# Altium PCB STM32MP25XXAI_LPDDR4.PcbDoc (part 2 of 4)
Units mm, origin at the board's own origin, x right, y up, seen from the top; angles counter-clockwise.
Board outline 172 x 137 mm, 4 copper layers (Top Layer, Signal Layer 1, Signal Layer 2, Bottom Layer), stack 1.614 mm thick; 188 components, 144 nets, 1216 pads, 838 vias.
Unrouted connection lines stored in the file: 13.
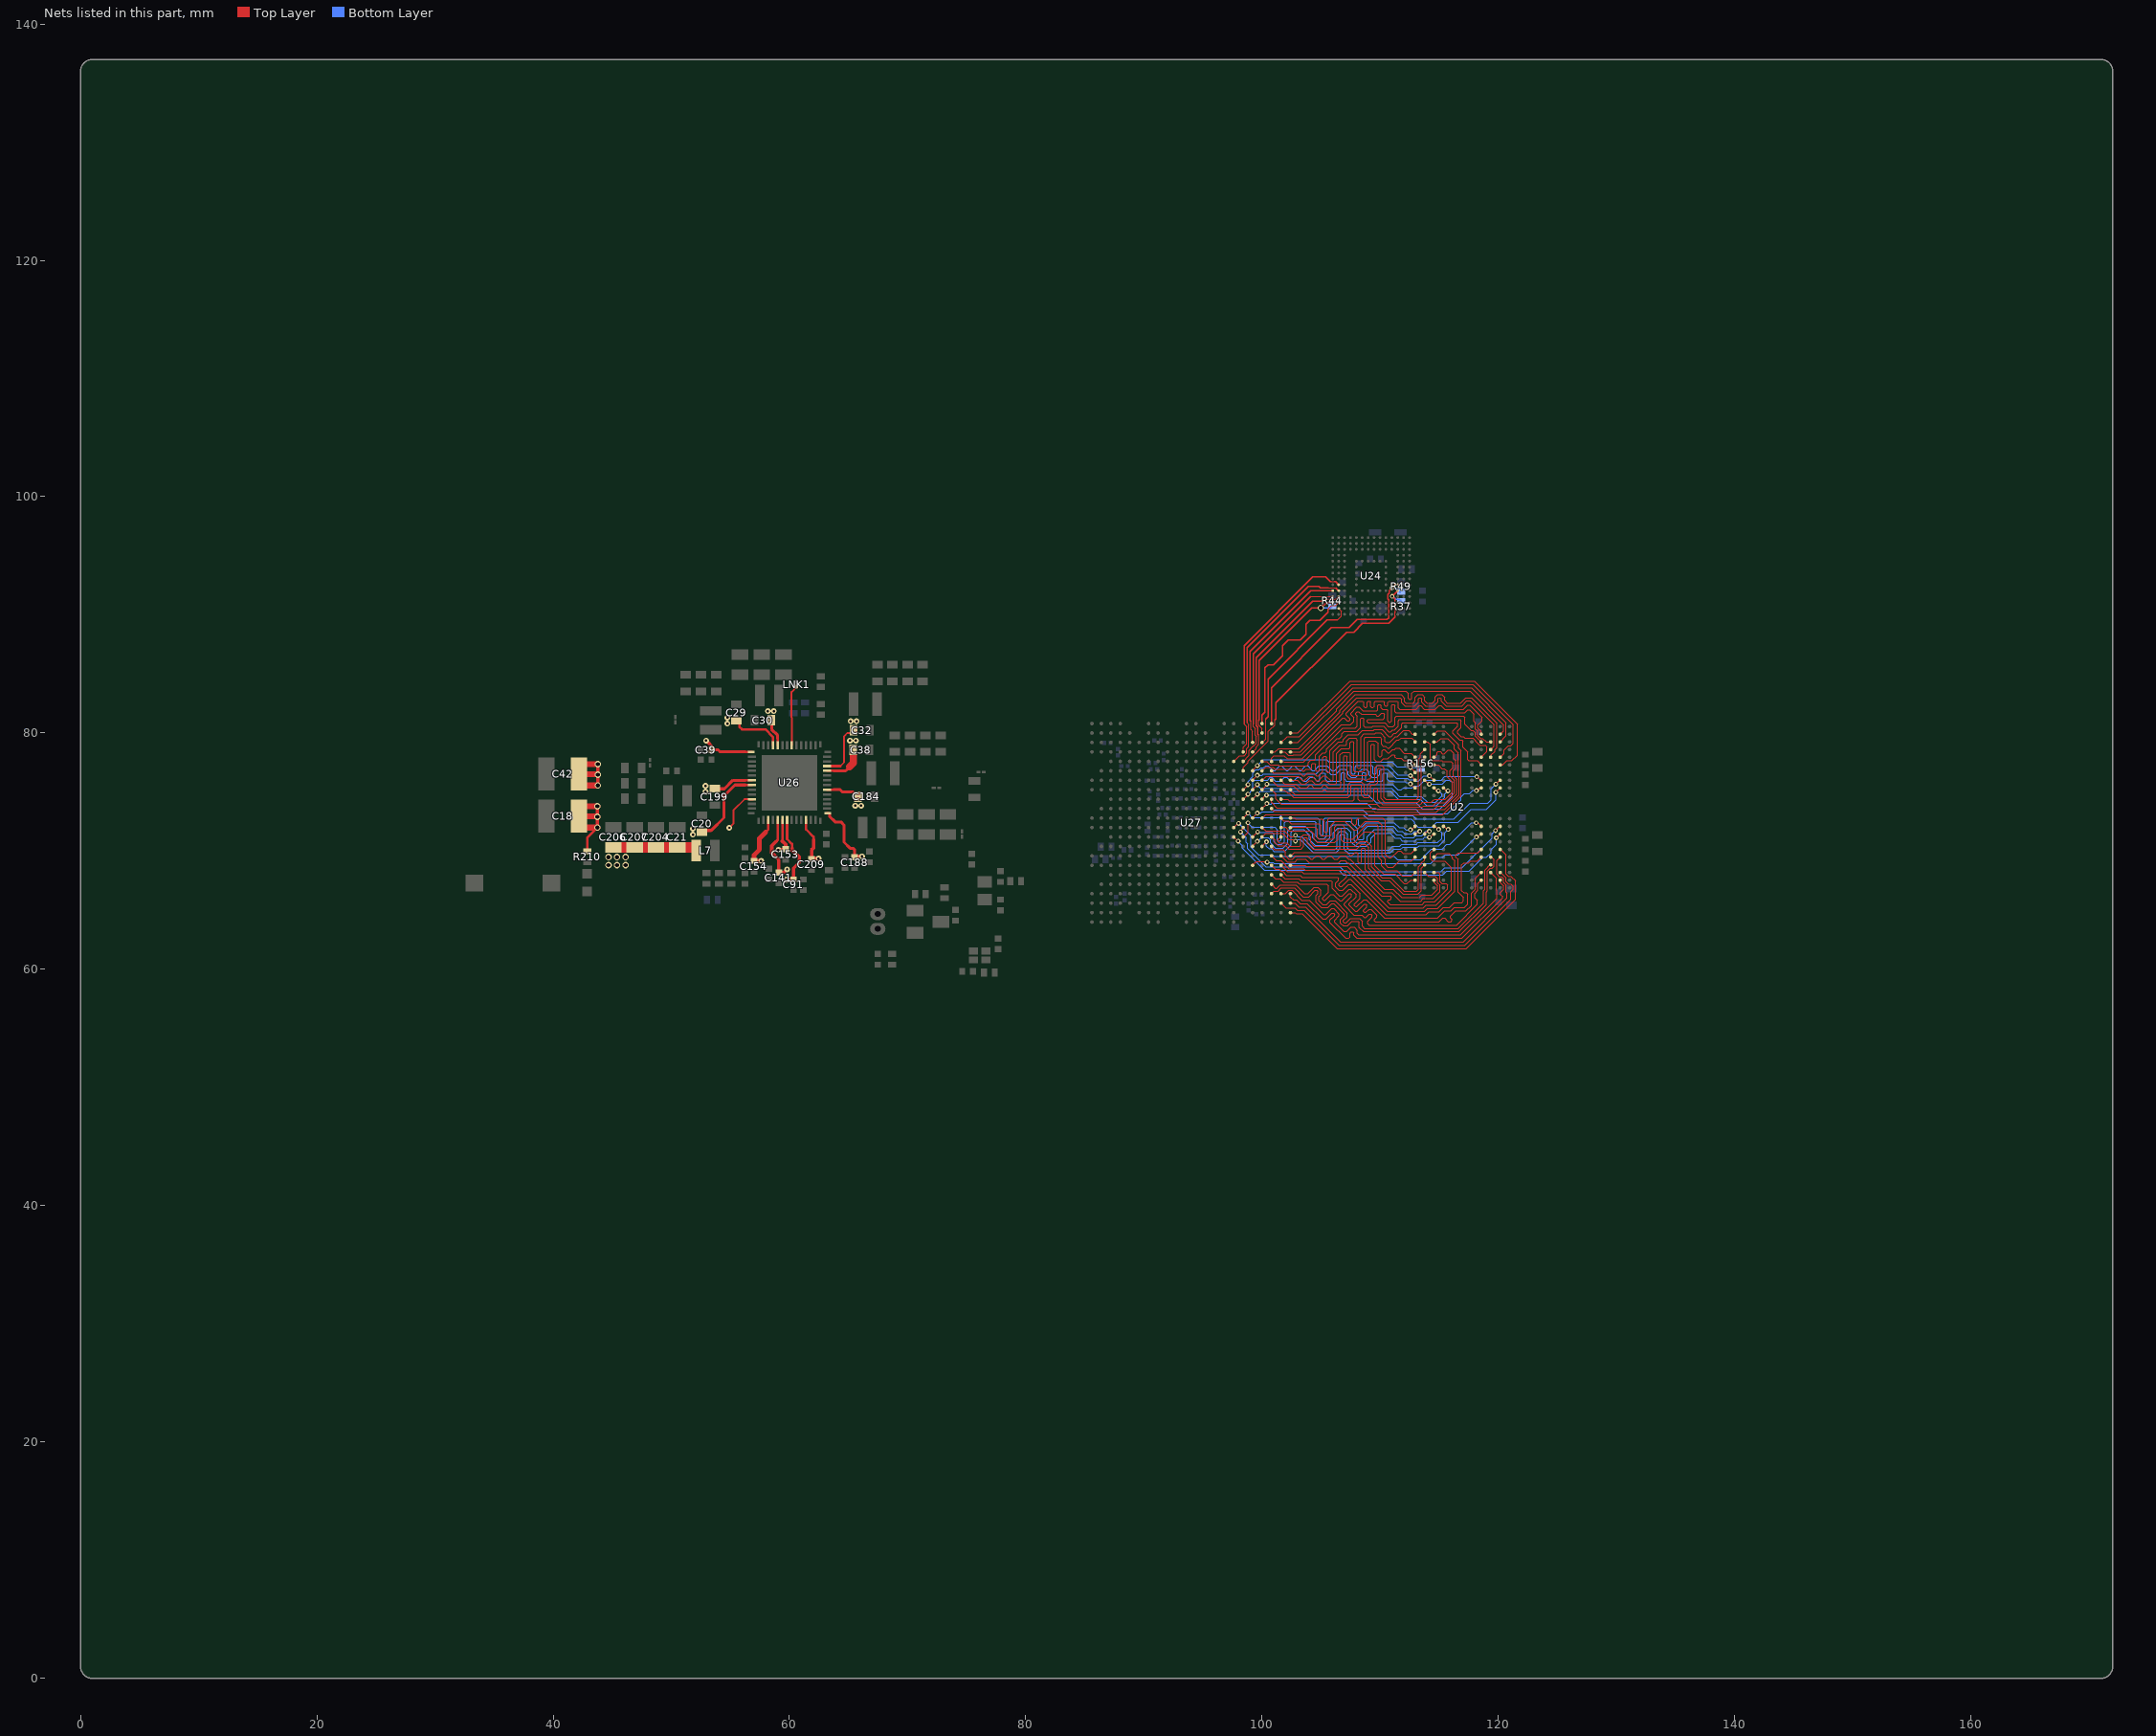
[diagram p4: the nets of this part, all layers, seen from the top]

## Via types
v1: diameter 0.55, hole 0.35, Top Layer to Bottom Layer, 387 vias
v2: diameter 0.4, hole 0.2, Top Layer to Bottom Layer, tented both sides, 173 vias
v3: diameter 0.5, hole 0.2, Top Layer to Bottom Layer, 146 vias
v4: diameter 0.4, hole 0.2, Top Layer to Bottom Layer, 129 vias
v5: diameter 0.5, hole 0.25, Top Layer to Bottom Layer, 3 vias

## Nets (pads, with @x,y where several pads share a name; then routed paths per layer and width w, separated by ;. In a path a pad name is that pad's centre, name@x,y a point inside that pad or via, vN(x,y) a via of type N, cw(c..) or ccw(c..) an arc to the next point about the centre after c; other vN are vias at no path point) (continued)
1V8_FB: LNK1.1 U26.35 | length 5.1
  Top Layer w0.15: U26.35@60.2,78.97 60.2,81.311 60.175,81.336 60.175,83.473 LNK1.1@60.6,83.898
3V3: C21.2 C154.2 C204.2 C206.2 C207.2 L7.2 U26.3 U26.53 | length 15.3
  Top Layer w0.15: v3(54.91,71.977) 55.262,72.329 55.262,73.465 56.197,74.4 U26.53@56.83,74.4 ; U26.53@56.62,74.369 56.919,74.369 U26.53@56.95,74.4
  Top Layer w0.21: 57.973,71.598 58.2,71.825 U26.3@58.2,72.63
  Top Layer w0.3: C154.2@56.975,69.175 C154.2@57,69.175 v3@57.585,69.175
  Top Layer w0.4: C154.2@57,69.175 57.014,69.189 57.014,69.685 57.46,70.131 57.46,71.085 57.973,71.598
  Top Layer w0.9: C206.2@45.087,70.323 C21.2@50.5,70.323 51.862,70.323 L7.2@51.887,70.298
  other v1: 44.687,68.823 45.412,68.823 46.137,68.823 44.687,69.498 45.412,69.498 46.137,69.498
  other v3: 57.61,69.175
5V_HDMI: C91.1 U26.7 | length 6.1
  Top Layer w0.21: U26.7@59.8,72.63 59.8,71.025 60.215,70.61 60.215,70.253
  Top Layer w0.3: v3(59.74,67.58) C91.1@60.35,67.58 ; 60.215,70.253 60.215,70.118 60.835,69.498 60.835,69.035 60.35,68.55 C91.1@60.35,67.73
5V_STLK: C18.1 C20.2 C29.2 C30.2 C32.2 C38.2 C39.2 C42.1 C153.2 C184.2 C188.2 C199.2 C209.2 R210.1 U26.6 U26.11 U26.15 U26.20 U26.24 U26.25 U26.38 U26.39 U26.43 U26.49 U26.50 | length 60.9
  Top Layer w0.15: 64.3,77.2 64.625,77.525 64.625,79.731 64.888,79.994 65.319,79.994 C32.2@65.425,80.1
  Top Layer w0.2: R210.1@42.887,69.97 42.887,71.138 v1(43.751,72.002)
  Top Layer w0.21: C29.2@55.525,81.05 55.762,80.813 55.762,80.513 55.975,80.3 57.964,80.3 58.6,79.664 U26.39@58.6,78.97 ; 56.275,75.6 U26.50@56.83,75.6 ; 56.275,76 U26.49@56.83,76 ; 56.275,78.4 U26.43@56.83,78.4 ; U26.38@59,78.97 59,79.525 ; 59.4,70.85 U26.6@59.4,72.63 ; U26.11@61.4,72.63 61.4,71.843 62.04,71.203 62.04,70.975 ; U26.15@63.17,73.2 U26.15@63.245,73.2 U26.15@63.285,73.2 ; U26.20@63.17,75.2 63.725,75.2 ; U26.24@63.17,76.8 63.725,76.8 ; U26.25@63.17,77.2 64.3,77.2
  Top Layer w0.25: C20.2@52.6,71.75 53.375,71.75 54.45,72.825 54.45,74.669 55.381,75.6 56.275,75.6 ; 53.195,79.125 53.199,79.125 53.345,78.979 53.345,78.685 C39.2@53.455,78.575 ; C39.2@53.505,78.575 53.975,78.575 54.15,78.4 56.275,78.4 ; C199.2@53.675,75.275 54.491,75.275 55.216,76 56.275,76 ; C30.2@58.425,81.075 58.494,81.006 58.494,80.308 59,79.802 59,79.525 ; 63.395,73.095 63.395,72.947 63.871,72.472 64.353,72.472 64.625,72.2 64.625,70.759 65.134,70.25 65.379,70.25 65.525,70.104 C188.2@65.525,69.55 ; 63.725,75.2 64.288,75.2 64.463,75.025 65.347,75.025 65.472,74.9 65.55,74.9 65.747,74.703 C184.2@65.747,74.625 ; 63.725,76.8 64.75,76.8 65.075,77.125
  Top Layer w0.3: v1(43.751,72.002) v1(43.751,72.902) v1(43.751,73.802) ; v1(43.776,75.565) v1(43.776,76.465) v1(43.776,77.365) ; v3@52.944,79.376 53.195,79.125 ; v3(59.065,70.11) 59.675,70.11 59.674,70.111 59.674,70.576 59.4,70.85 ; C209.2@61.85,69.38 C209.2@61.875,69.38 ; 62.04,70.975 62.04,70.269 61.875,70.104 C209.2@61.875,69.38 ; v3(62.46,69.38) C209.2@61.875,69.38 ; C188.2@65.525,69.55 v3(66.135,69.55)
  Top Layer w0.5: C18.1@42.187,72.049 42.235,72.002 v1(43.751,72.002) ; C18.1@42.187,72.961 43.679,72.961 43.737,72.902 v1(43.751,72.902) ; C42.1@42.187,75.612 42.235,75.565 v1(43.776,75.565) ; C42.1@42.187,76.523 43.704,76.523 43.762,76.465 v1(43.776,76.465) ; C18.1@42.246,73.802 v1(43.751,73.802) ; C42.1@42.246,77.365 v1(43.776,77.365)
  Top Layer w0.6: 65.075,77.125 65.4,77.45 C38.2@65.4,78.175
  other v3: 51.825,71.4 51.825,71.9 65.575,73.85 66.075,73.85 52.9,75.025 52.9,75.525 52.95,79.348 65.125,79.35 65.625,79.35 54.75,80.8 65.175,81 65.675,81 54.75,81.3 58.175,81.85 58.675,81.85
5V_VCONN: C141.1 U26.5 | length 5.7
  Top Layer w0.21: 58.877,70.828 59,70.95 U26.5@59,72.63
  Top Layer w0.3: 58.877,70.828 58.51,70.46 58.51,69.865 59.1,69.275 C141.1@59.1,68.2 59.539,68.2 v3(59.8,68.46)
DDR_CA0_A: U2.H2 U27.N16 | length 25.9
  Top Layer w0.09: U27.N16@97.6,71.2 97.95,70.85 v4(97.975,70.85) ; v4(119.825,71.125) U2.H2@120.15,71.45
  Bottom Layer w0.09: v4@97.975,70.825 98.347,70.453 98.347,70.255 100.212,68.39 106.49,68.39 106.893,67.988 115.285,67.988 115.604,68.307 117.532,68.307 118.705,69.48 118.993,69.48 119.375,69.862 119.375,70.125 119.825,70.575 v4(119.825,71.125)
DDR_CA0_B: U2.R2 U27.L18 | length 23.5
  Top Layer w0.09: v4(119.775,75.675) 120.1,76 U2.R2@120.15,76
  Top Layer w0.1: U27.L18@99.2,72.8 99.6,73.2 v4(99.6,73.225)
  Bottom Layer w0.09: v4@99.6,73.2 99.608,73.208 99.882,73.208 99.999,73.325 100.925,73.325 101.092,73.492 108.549,73.492 109.041,73 112.743,73 113.023,72.72 116.232,72.72 117.592,74.08 119.093,74.08 119.375,74.362 119.375,75.275 v4(119.775,75.675)
DDR_CA1_A: U2.J2 U27.M17 | length 26.1
  Top Layer w0.09: v4(98.175,71.625) 98.235,71.684 98.235,71.784 98.4,71.95 U27.M17@98.4,72 ; v4(119.75,71.75) 119.775,71.75 120.125,72.1 U2.J2@120.15,72.1
  Bottom Layer w0.09: v4(98.175,71.625) 98.637,71.164 98.637,70.757 98.782,70.612 98.782,70.231 100.332,68.68 106.611,68.68 107.013,68.278 115.128,68.278 115.447,68.597 116.935,68.597 119.45,71.112 119.45,71.45 v4(119.75,71.75)
DDR_CA1_B: U2.P2 U27.L17 | length 24.4
  Top Layer w0.09: v4(119.775,74.975) U2.P2@120.15,75.35
  Top Layer w0.1: U27.L17@98.4,72.8 98.8,73.2 v4(98.8,73.225)
  Bottom Layer w0.09: v4@98.8,73.2 99.145,72.855 101.432,72.855 101.687,73.11 108.521,73.11 108.921,72.71 112.638,72.71 112.693,72.655 112.913,72.435 112.913,72.324 113.207,72.03 114.388,72.03 114.788,72.43 116.578,72.43 117.693,73.545 118.968,73.545 119.775,74.352 v4(119.775,74.975)
DDR_CA2_A: U2.H9 U27.P19 | length 20.6
  Top Layer w0.09: v4(114.15,71.175) 114.216,71.175 114.409,71.368 114.412,71.368 114.494,71.45 U2.H9@114.55,71.45
  Top Layer w0.1: U27.P19@100,70.4 100.375,70.775 v4(100.375,70.8)
  Bottom Layer w0.09: v4@100.375,70.775 100.375,70.42 100.593,70.202 100.798,70.202 101.016,69.984 101.903,69.984 102.465,70.547 102.465,71.593 102.701,71.828 103.51,71.828 104.003,71.336 104.003,70.966 104.472,70.497 105.499,70.497 106.044,71.042 106.044,71.558 106.436,71.95 107.147,71.95 107.516,71.581 107.516,70.792 107.908,70.4 108.815,70.4 109.208,70.792 109.208,71.091 109.646,71.53 110.827,71.53 111.247,71.11 111.633,71.11 111.868,70.875 112.937,70.875 113.097,71.035 113.637,71.035 113.777,71.175 v4(114.15,71.175)
DDR_CA2_B: U2.R9 U27.G18 | length 18.6
  Top Layer w0.09: v4(114.15,76.375) 114.175,76.375 U2.R9@114.55,76
  Top Layer w0.1: U27.G18@99.2,76 99.6,76.4 v4(99.6,76.425)
  Bottom Layer w0.09: v4@99.6,76.4 100,76.4 100.125,76.525 104.549,76.525 104.938,76.914 105.39,76.914 105.809,76.495 106.223,76.495 106.664,76.936 ; 106.681,76.952 107.02,76.952 107.29,76.682 107.29,76.475 107.535,76.23 107.91,76.23 108.16,76.48 108.16,76.678 108.434,76.952 108.833,76.952 109.078,76.707 109.078,76.467 109.315,76.23 109.7,76.23 109.948,76.478 109.948,76.798 110.102,76.952 110.59,76.952 111.377,76.165 112.287,76.165 112.407,76.045 112.84,76.045 112.97,75.914 113.228,75.914 113.688,76.375 v4(114.15,76.375)
DDR_CA3_A: U2.H10 U27.P18 | length 21.7
  Top Layer w0.09: U2.H10@113.75,71.45 113.924,71.624 114.099,71.624 v4(114.15,71.675)
  Top Layer w0.1: U27.P18@99.2,70.425 v4(99.6,70.825)
  Bottom Layer w0.09: v4@99.6,70.8 99.945,71.145 100.518,71.145 100.632,71.03 100.636,71.03 100.725,70.941 100.725,70.685 101.136,70.274 101.783,70.274 102.175,70.667 102.175,71.713 102.58,72.118 103.63,72.118 104.293,71.456 104.293,71.162 104.668,70.787 105.379,70.787 105.754,71.162 105.754,71.989 106.005,72.24 107.331,72.24 107.806,71.766 107.806,70.913 108.028,70.69 108.695,70.69 108.918,70.913 108.918,71.212 109.526,71.82 110.947,71.82 111.367,71.4 111.753,71.4 111.988,71.165 112.817,71.165 112.977,71.325 113.497,71.325 113.847,71.675 v4(114.15,71.675)
DDR_CA3_B: U2.R10 U27.J19 | length 21
  Top Layer w0.09: U2.R10@113.75,76 113.774,76 114.099,75.675 v4(114.15,75.675)
  Top Layer w0.1: U27.J19@100,74.4 100.335,74.735 v4(100.375,74.735)
  Bottom Layer w0.09: v4@100.375,74.75 109,74.75 109.655,74.095 113.044,74.095 113.554,73.585 115.04,73.585 116.095,74.64 116.095,75.793 115.868,76.02 115.582,76.02 115.237,75.675 v4(114.15,75.675)
DDR_CA4_A: U2.H11 U27.N18 | length 22.3
  Top Layer w0.09: U2.H11@112.95,71.45 112.956,71.45 113.108,71.602 113.193,71.602 113.266,71.675 v4(113.35,71.675)
  Top Layer w0.1: U27.N18@99.2,71.2 v4(99.625,71.625)
  Bottom Layer w0.09: v4@99.625,71.6 100.833,71.6 101.015,71.418 101.015,70.805 101.256,70.564 101.663,70.564 101.885,70.787 101.885,72.382 102.033,72.53 104.448,72.53 104.583,72.395 104.583,71.282 104.788,71.077 105.259,71.077 105.464,71.282 105.464,72.447 105.547,72.53 107.452,72.53 108.096,71.886 108.096,71.054 108.17,70.98 108.528,70.98 108.628,71.079 108.628,71.802 108.936,72.11 111.067,72.11 111.487,71.69 111.873,71.69 112.108,71.455 112.697,71.455 112.917,71.675 v4(113.35,71.675)
DDR_CA4_B: U2.R11 U27.H17 | length 20.5
  Top Layer w0.09: v4@112.55,76.425 112.57,76.425 112.95,76.045 U2.R11@112.95,76
  Top Layer w0.1: U27.H17@98.4,75.2 98.8,75.6 v4(98.8,75.625)
  Bottom Layer w0.09: v4@98.8,75.6 98.8,75.893 99.216,76.309 99.216,76.632 99.464,76.88 99.755,76.88 99.925,77.05 100.125,77.05 100.3,77.225 100.526,77.225 100.936,76.815 101.077,76.815 101.482,77.22 101.633,77.22 102.038,76.815 102.184,76.815 102.594,77.225 102.732,77.225 103.142,76.815 103.306,76.815 103.696,77.204 103.873,77.204 104.262,76.815 104.429,76.815 104.818,77.204 105.51,77.204 105.886,76.828 106.146,76.828 106.56,77.242 107.485,77.242 107.58,77.147 107.58,76.595 107.655,76.52 107.79,76.52 107.87,76.6 107.87,77.137 107.975,77.242 109.268,77.242 109.368,77.142 109.368,76.587 109.436,76.52 109.58,76.52 109.658,76.598 109.658,77.145 109.754,77.242 110.72,77.242 111.507,76.455 112.52,76.455 112.55,76.425 v4@112.52,76.456
  other v4: 112.55,76.39
DDR_CA5_A: U2.J11 U27.N17 | length 22.2
  Top Layer w0.09: v4(112.55,71.8) 112.61,71.859 112.71,71.859 U2.J11@112.95,72.1
  Top Layer w0.1: U27.N17@98.4,71.2 98.8,71.6 v4(98.8,72.4)
  Bottom Layer w0.09: v4@98.8,72.375 99.15,72.025 101.075,72.025 101.305,71.795 101.305,70.948 101.399,70.854 101.508,70.854 101.595,70.941 101.595,72.608 101.807,72.82 104.699,72.82 104.873,72.647 104.873,71.441 104.947,71.367 105.093,71.367 105.174,71.448 105.174,72.654 105.34,72.82 108.073,72.82 108.179,72.714 108.179,72.213 108.329,72.063 108.478,72.063 108.815,72.4 111.187,72.4 111.607,71.98 111.994,71.98 112.17,71.803 112.547,71.803 v4(112.55,71.8)
DDR_CA5_B: U2.P11 U27.J17 | length 21.4
  Top Layer w0.09: v4@112.55,75.7 112.9,75.35 U2.P11@112.95,75.35
  Top Layer w0.1: U27.J17@98.4,74.4 98.8,74.8 v4(98.8,74.825)
  Bottom Layer w0.09: v4@98.8,74.8 99.239,75.239 99.239,75.874 99.386,76.022 100.458,76.022 100.671,76.235 100.846,76.235 101.141,75.94 101.581,75.94 101.876,76.235 102.108,76.235 102.403,75.94 102.676,75.94 102.971,76.235 103.238,76.235 103.533,75.94 103.775,75.94 104.07,76.235 104.353,76.235 104.648,75.94 104.801,75.94 104.905,76.045 104.905,76.472 105.058,76.624 105.263,76.624 105.367,76.52 105.367,76.056 105.483,75.94 106.594,75.94 106.71,76.057 106.71,76.571 106.802,76.662 106.9,76.662 107,76.562 107,76.067 107.128,75.94 108.362,75.94 108.475,76.053 108.475,76.583 108.555,76.662 108.713,76.662 108.778,76.597 108.778,76.019 108.857,75.94 110.147,75.94 110.238,76.031 110.238,76.53 110.332,76.625 110.507,76.625 110.6,76.532 110.6,76.09 110.75,75.94 111.157,75.94 111.227,75.87 112.113,75.87 112.193,75.79 112.495,75.79 v4@112.55,75.735
  other v4: 112.55,75.69
DDR_CKE0_A: U2.J4 U27.M16 | length 24.4
  Top Layer w0.09: U27.M16@97.6,72 97.615,72 97.965,72.35 v4(98.025,72.35) ; v4(118.125,72.4) 118.185,72.341 118.31,72.341 U2.J4@118.55,72.1
  Bottom Layer w0.09: v4(98.025,72.35) 99.072,71.304 99.072,70.351 99.719,69.703 100.867,69.703 101.001,69.57 111.169,69.57 111.459,69.28 113.424,69.28 114.329,70.185 115.264,70.185 115.641,70.561 115.9,70.561 117.738,72.4 v4(118.125,72.4) ; v4@118.125,72.375 v4@118.175,72.375
DDR_CKE0_B: U2.P4 U27.K19 | length 20.2
  Top Layer w0.09: v4(118.15,75.125) 118.357,75.332 118.532,75.332 U2.P4@118.55,75.35
  Top Layer w0.1: U27.K19@100,73.6 100.4,74 v4(100.4,74.025)
  Bottom Layer w0.09: v4@100.4,74 100.773,74 100.845,74.072 108.858,74.072 109.35,73.58 112.983,73.58 113.373,73.19 115.705,73.19 116.845,74.33 116.845,74.578 117.122,74.855 117.581,74.855 117.862,75.137 v4@118.15,75.137 ; v4@118.15,75.125 v4@118.15,75.137 ; v4@118.15,75.175 v4@118.15,75.137
DDR_CLK_A_N: U2.J9 U27.M19 | length 20.4
  Top Layer w0.09: U27.M19@100,72 100.295,71.705 101.89,71.705 102.363,71.232 102.623,71.232 102.741,71.35 v4(102.825,71.35) ; U2.J9@114.55,72.1 114.607,72.1 114.798,71.909 114.891,71.909 v4(114.95,71.85)
  Bottom Layer w0.09: v4@102.909,71.325 102.934,71.325 103.034,71.225 103.334,71.225 104.434,70.125 106.157,70.125 106.334,70.302 106.334,71.407 106.587,71.66 106.98,71.66 107.226,71.414 107.226,70.251 107.367,70.11 110.754,70.11 111.054,70.41 111.643,70.41 111.818,70.585 113.058,70.585 113.198,70.725 114.865,70.725 115.206,71.066 115.206,71.551 114.95,71.806 v4(114.95,71.85)
DDR_CLK_A_P: U2.J8 U27.N19 | length 20.9
  Top Layer w0.09: U27.N19@100,71.2 100.295,71.495 101.747,71.495 102.268,70.974 102.617,70.974 102.741,70.85 v4(102.825,70.85) ; U2.J8@115.35,72.1 115.388,72.1 115.579,71.909 115.691,71.909 v4(115.75,71.85)
  Bottom Layer w0.09: v4(102.825,70.85) 102.908,70.85 103.033,70.975 103.23,70.975 104.33,69.875 106.26,69.875 106.584,70.198 106.584,71.304 106.69,71.41 106.877,71.41 106.976,71.311 106.976,70.147 107.263,69.86 109.265,69.86 110.857,69.86 111.157,70.16 111.747,70.16 111.922,70.335 113.161,70.335 113.301,70.475 114.969,70.475 115.456,70.962 115.456,71.556 v4(115.75,71.85)
DDR_CLK_B_N: U2.P9 U27.H18 | length 18.1
  Top Layer w0.09: U2.P9@114.55,75.35 114.558,75.35 114.749,75.159 114.866,75.159 v4(114.925,75.1)
  Top Layer w0.1: U27.H18@99.2,75.2 99.6,75.6 v4(99.6,75.625)
  Bottom Layer w0.09: v4@99.6,75.6 99.87,75.33 110.947,75.33 111.289,74.988 111.632,74.645 113.487,74.645 114.007,74.125 114.676,74.125 115.213,74.663 115.213,74.812 v4(114.925,75.1)
DDR_CLK_B_P: U2.P8 U27.J18 | length 18.5
  Top Layer w0.09: U2.P8@115.35,75.35 115.363,75.35 115.554,75.159 115.641,75.159 v4@115.725,75.075
  Top Layer w0.1: U27.J18@99.2,74.4 99.6,74.8 v4(99.6,74.825)
  Bottom Layer w0.09: v4(99.6,74.825) 99.855,75.08 110.844,75.08 111.529,74.395 113.384,74.395 113.904,73.875 114.779,73.875 115.463,74.559 115.463,74.838 v4(115.725,75.1)
DDR_CS0_A: U2.H4 U27.T18 | length 20.6
  Top Layer w0.09: U27.T18@99.2,68.825 99.495,69.12 100.38,69.12 v4(100.425,69.075) ; v4(118.15,71.2) 118.21,71.259 118.304,71.259 118.494,71.45 U2.H4@118.55,71.45
  Bottom Layer w0.09: v4(100.425,69.075) 100.444,69.056 100.932,69.056 101.017,68.97 114.288,68.97 114.803,69.485 115.295,69.485 115.512,69.701 116.602,69.701 118.1,71.2 v4@118.15,71.2
DDR_CS0_B: U2.R4 U27.H19 | length 19.6
  Top Layer w0.09: v4(118.175,76.305) 118.211,76.305 118.515,76 U2.R4@118.55,76
  Top Layer w0.1: U27.H19@100,75.2 100.4,75.6 v4(100.4,75.675)
  Bottom Layer w0.09: v4@100.4,75.65 111.037,75.65 111.507,75.18 111.793,75.18 111.958,75.345 112.709,75.345 112.895,75.531 113.256,75.531 113.749,76.024 115.176,76.024 115.462,76.31 118.17,76.31 v4(118.175,76.305)
DDR_DQ0_A: U2.B2 U27.W22 | length 25
  Top Layer w0.09: U27.W22@102.4,66.4 102.4,66.14 102.65,65.89 102.917,65.89 103.247,65.56 103.81,65.56 105.118,64.252 105.418,64.252 105.911,64.745 106.048,64.745 106.131,64.662 106.131,64.544 105.757,64.17 105.757,63.938 107.07,62.625 107.325,62.625 107.425,62.725 107.425,63.067 107.52,63.162 107.679,63.162 107.771,63.07 107.771,62.869 108.015,62.625 116.923,62.625 120.34,66.041 120.34,66.161 120.175,66.325 120.175,66.508 120.45,66.783 120.45,67.065 120.169,67.346 120.169,67.529 U2.B2@120.149,67.549
DDR_DQ0_B: U2.AA2 U27.D20 | length 25
  Top Layer w0.09: U27.D20@100.8,78.4 101.102,78.4 101.397,78.695 103.107,78.695 106.293,81.881 106.293,82.037 107.785,83.53 112.199,83.53 112.375,83.353 112.375,82.918 112.458,82.835 112.602,82.835 112.679,82.912 112.679,83.357 112.851,83.53 117.588,83.53 120.445,80.672 120.445,80.195 U2.AA2@120.15,79.9
DDR_DQ1_A: U2.C2 U27.Y21 | length 25.5
  Top Layer w0.09: U27.Y21@101.6,65.6 102.003,65.197 102.79,65.197 103.007,64.98 103.57,64.98 106.505,62.045 117.164,62.045 121.034,65.915 121.034,66.566 121.245,66.778 121.245,67.022 121.043,67.225 120.858,67.225 120.655,67.428 120.655,67.731 120.186,68.2 U2.C2@120.15,68.2
DDR_DQ1_B: U2.Y2 U27.C22 | length 23.2
  Top Layer w0.09: U27.C22@102.4,79.2 103.046,79.2 107.665,83.82 117.71,83.82 120.655,80.875 120.655,79.755 U2.Y2@120.15,79.25
DDR_DQ2_A: U2.E2 U27.Y22 | length 25.3
  Top Layer w0.09: U27.Y22@102.4,65.6 102.797,65.6 103.127,65.27 103.69,65.27 106.625,62.335 117.044,62.335 120.744,66.035 120.744,66.434 120.64,66.538 120.64,67.143 120.445,67.338 120.445,67.672 120.273,67.845 120.088,67.845 119.855,68.078 119.855,69.205 U2.E2@120.15,69.5
DDR_DQ2_B: U2.V2 U27.C21 | length 26.4
  Top Layer w0.09: U27.C21@101.6,79.2 101.627,79.2 102.132,79.705 103.14,79.705 107.545,84.11 117.831,84.11 121.245,80.695 121.245,79.118 121.052,78.925 120.833,78.925 120.479,78.57 120.479,78.278 U2.V2@120.15,77.95
DDR_DQ3_A: U2.F2 U27.AA22 | length 26.9
  Top Layer w0.09: U27.AA22@102.4,64.8 102.777,64.8 102.886,64.69 103.403,64.69 106.339,61.755 117.284,61.755 121.435,65.907 121.435,67.482 121.043,67.875 120.858,67.875 120.655,68.078 120.655,69.681 120.186,70.15 U2.F2@120.15,70.15
DDR_DQ3_B: U2.U2 U27.B22 | length 27
  Top Layer w0.09: U27.B22@102.4,80 103.025,80 107.425,84.4 117.951,84.4 121.62,80.73 121.62,78.125 121.145,77.65 120.725,77.65 120.375,77.3 U2.U2@120.15,77.3
DDR_DQ4_A: U2.F4 U27.T21 | length 26
  Top Layer w0.09: U27.T21@101.6,68.8 U27.T21@101.6,68.8 102.146,68.255 103.366,68.255 103.51,68.112 106.996,68.112 107.142,67.966 107.142,67.816 106.526,67.201 106.526,67.081 106.608,66.999 106.737,66.999 107.346,67.608 107.499,67.608 110.493,64.615 113.897,64.615 114.137,64.855 114.973,64.855 115.353,65.235 115.869,65.235 116.284,65.65 116.903,65.65 117.041,65.788 117.041,66.086 116.6,66.527 116.6,69.309 116.411,69.498 116.411,69.673 116.593,69.855 118.255,69.855 U2.F4@118.55,70.15
DDR_DQ4_B: U2.U4 U27.F20 | length 27.5
  Top Layer w0.09: U27.F20@100.8,76.8 100.97,76.63 103.186,76.63 103.432,76.384 103.582,76.384 103.828,76.63 104.351,76.63 104.601,76.38 104.771,76.38 105.125,76.734 105.125,77.9 105.254,78.028 105.364,78.028 105.439,77.953 105.439,76.735 105.537,76.637 105.644,76.637 105.735,76.728 105.735,78.51 106.468,79.242 106.8,79.242 106.878,79.32 106.878,79.456 107.271,79.848 108.142,79.848 108.508,80.214 109.43,80.214 109.505,80.289 110.143,80.289 110.725,79.707 110.909,79.707 111.177,79.975 111.33,79.975 111.815,80.46 111.815,80.76 111.9,80.845 116.455,80.845 116.56,80.74 116.56,80.579 116.157,80.175 116.157,79.969 116.726,79.399 116.912,79.399 117.005,79.306 117.005,78.788 117.386,78.407 117.386,77.75 117.486,77.65 118.2,77.65 U2.U4@118.55,77.3
DDR_DQ5_A: U2.E4 U27.T20 | length 27.5
  Top Layer w0.09: U27.T20@100.8,68.8 101.113,68.487 101.438,68.487 101.63,68.295 101.726,68.295 102.056,67.965 103.246,67.965 103.411,67.8 106.375,67.8 106.472,67.703 106.472,67.557 106.213,67.298 106.213,66.983 106.515,66.682 106.83,66.682 107.314,67.166 107.531,67.166 108.296,66.401 108.296,65.987 107.811,65.502 107.811,65.398 107.913,65.296 108.022,65.296 108.611,65.886 108.811,65.886 110.372,64.325 114.853,64.325 115.473,64.945 115.989,64.945 116.287,65.243 117.137,65.243 117.42,65.526 117.42,66.36 117.284,66.497 117.063,66.497 116.89,66.67 116.89,68.839 117.069,69.018 117.493,69.018 117.64,69.165 118.215,69.165 U2.E4@118.55,69.5
DDR_DQ5_B: U2.V4 U27.F19 | length 28.2
  Top Layer w0.09: U27.F19@100,76.8 100.3,77.1 100.924,77.1 101.104,76.92 103.306,76.92 103.451,76.775 103.563,76.775 103.708,76.92 104.134,76.92 104.218,77.004 104.218,77.331 104.294,77.407 104.446,77.407 104.525,77.327 104.525,76.866 104.616,76.775 104.756,76.775 104.834,76.853 104.834,78.018 105.134,78.318 105.338,78.318 105.445,78.426 105.445,78.63 106.347,79.532 106.544,79.532 106.736,79.723 106.736,79.92 106.954,80.138 108.022,80.138 108.333,80.449 108.333,81.19 108.427,81.284 108.539,81.284 108.625,81.198 108.625,80.585 108.706,80.504 109.309,80.504 109.385,80.579 110.263,80.579 110.734,80.108 110.901,80.108 111.057,80.265 111.21,80.265 111.525,80.58 111.525,81.036 111.625,81.135 116.756,81.135 116.85,81.041 116.85,80.459 116.558,80.167 116.558,79.977 116.846,79.689 117.032,79.689 117.154,79.567 117.85,79.567 118.045,79.372 118.045,79.338 118.436,78.947 118.886,78.947 119.033,78.8 119.033,78.433 U2.V4@118.55,77.95
DDR_DQ6_A: U2.C4 U27.U21 | length 26.3
  Top Layer w0.09: U27.U21@101.6,68 101.925,67.675 103.126,67.675 103.291,67.51 105.819,67.51 105.923,67.406 105.923,66.863 106.565,66.222 106.779,66.222 107.347,66.789 107.498,66.789 107.952,66.336 107.952,66.143 107.355,65.545 107.355,65.445 107.885,64.914 108.05,64.914 108.651,65.516 108.771,65.516 108.856,65.431 108.856,65.281 108.582,65.007 108.582,64.893 108.665,64.811 108.786,64.811 109.056,65.081 109.206,65.081 109.7,64.588 109.7,64.414 109.499,64.214 109.499,64.112 109.576,64.035 114.973,64.035 115.286,64.347 115.446,64.347 115.759,64.035 115.97,64.035 116.064,64.129 116.064,64.239 115.943,64.361 115.943,64.489 116.407,64.953 117.257,64.953 117.71,65.406 117.71,66.443 118.057,66.789 118.057,67.706 U2.C4@118.55,68.2 ; U2.C4@118.513,68.238 U2.C4@118.55,68.275
DDR_DQ6_B: U2.Y4 U27.E19 | length 27.7
  Top Layer w0.09: U27.E19@100,77.6 100.376,77.6 100.676,77.3 101.367,77.3 101.432,77.235 103.805,77.235 103.928,77.357 103.928,77.522 104.103,77.697 104.426,77.697 104.544,77.815 104.544,78.138 106.834,80.428 107.902,80.428 108.043,80.569 108.043,81.424 107.927,81.54 107.927,81.677 108.056,81.806 108.187,81.806 108.419,81.574 109.579,81.574 109.703,81.45 109.878,81.45 110.12,81.692 110.273,81.692 110.365,81.6 110.365,81.275 110.25,81.16 108.993,81.16 108.915,81.082 108.915,80.943 108.988,80.869 110.383,80.869 110.697,80.555 111.09,80.555 111.235,80.7 111.235,81.296 111.364,81.425 117.05,81.425 117.155,81.32 117.155,80.728 117.668,80.215 117.852,80.215 118.038,80.03 118.038,79.741 118.529,79.25 U2.Y4@118.55,79.25
DDR_DQ7_A: U2.B4 U27.U20 | length 27.1
  Top Layer w0.09: U27.U20@100.8,68 101.138,67.662 101.528,67.662 101.805,67.385 103.006,67.385 103.12,67.271 103.171,67.22 105.471,67.22 105.633,67.058 105.633,66.549 105.13,66.045 105.13,65.93 105.219,65.84 105.34,65.84 105.838,66.337 106.039,66.337 106.2,66.176 106.593,65.783 106.751,65.783 107.363,66.395 107.483,66.395 107.55,66.327 107.55,66.151 106.953,65.554 106.953,65.424 107.778,64.598 108.467,64.598 108.67,64.395 108.78,64.395 109.05,64.664 109.213,64.664 109.314,64.563 109.314,64.438 108.955,64.079 108.955,63.871 109.08,63.745 116.459,63.745 118.225,65.511 118.225,65.825 118,66.05 118,66.425 118.255,66.68 118.255,67.255 U2.B4@118.55,67.55
DDR_DQ7_B: U2.AA4 U27.E20 | length 27.1
  Top Layer w0.09: U27.E20@100.8,77.6 100.8,77.858 101.009,78.067 101.865,78.067 102.117,77.815 103.4,77.815 106.2,80.615 106.837,81.252 106.967,81.252 107.211,81.008 107.362,81.008 107.449,81.095 107.449,81.198 107.123,81.524 107.123,81.693 108.129,82.7 108.536,82.7 108.607,82.629 108.607,82.234 108.687,82.154 108.815,82.154 108.905,82.244 108.905,82.608 108.997,82.7 109.125,82.7 109.2,82.625 109.2,82.236 109.282,82.154 109.399,82.154 109.495,82.25 109.495,82.613 109.582,82.7 110.285,82.7 110.365,82.619 110.365,82.35 110.443,82.273 110.563,82.273 110.655,82.365 110.655,82.606 110.749,82.7 111.424,82.7 111.531,82.592 111.531,82.114 111.64,82.005 113.024,82.005 113.322,82.303 113.429,82.303 113.727,82.005 114.647,82.005 114.97,82.328 115.129,82.328 115.451,82.005 117.026,82.005 117.386,82.365 117.561,82.365 118.625,81.3 118.625,81.042 118.255,80.672 118.255,80.428 118.55,80.133 U2.AA4@118.55,79.9
DDR_DQ8_A: U2.B11 U27.M21 | length 18.1
  Top Layer w0.09: U27.M21@101.6,72 101.625,72.025 101.958,72.025 102.278,71.705 104.125,71.705 104.4,71.43 104.4,71.03 104.705,70.725 106.165,70.725 106.43,70.99 106.43,71.858 106.508,71.935 106.638,71.935 106.723,71.85 106.723,70.927 106.925,70.725 107.787,70.725 108.675,71.613 109.44,71.613 109.555,71.497 109.555,68.777 110.281,68.051 111.232,68.051 112.028,67.255 112.273,67.255 112.568,67.55 U2.B11@112.95,67.55
DDR_DQ8_B: U2.AA11 U27.G19 | length 23.2
  Top Layer w0.09: U27.G19@100,76 100.34,76.34 103.066,76.34 103.451,75.955 103.563,75.955 103.948,76.34 104.231,76.34 104.616,75.955 104.756,75.955 105.185,76.384 105.38,76.384 105.809,75.955 105.95,75.955 106.025,76.03 106.025,78.389 106.588,78.952 107.07,78.952 107.168,79.05 107.168,79.335 107.391,79.558 107.928,79.558 108.061,79.425 108.061,77.076 108.129,77.009 108.29,77.009 108.369,77.087 108.369,79.665 108.628,79.924 109.55,79.924 109.625,79.999 110.023,79.999 110.395,79.627 110.395,79.304 110.509,79.19 110.802,79.19 111.297,79.685 111.45,79.685 111.965,80.2 112.425,80.2 112.725,79.9 U2.AA11@112.95,79.9
DDR_DQ9_A: U2.C11 U27.M22 | length 17.7
  Top Layer w0.09: U27.M22@102.4,72 102.44,72.04 104.478,72.04 104.69,71.828 104.69,71.15 104.825,71.015 105.997,71.015 106.14,71.159 106.14,72.021 106.344,72.225 106.795,72.225 107.013,72.007 107.013,71.157 107.156,71.015 107.667,71.015 108.877,72.225 109.716,72.225 109.845,72.096 109.845,69.505 110.133,69.217 110.133,68.749 110.526,68.357 111.424,68.357 111.875,67.905 112.655,67.905 U2.C11@112.95,68.2 ; U2.C11@112.913,68.238 U2.C11@112.95,68.275
DDR_DQ9_B: U2.Y11 U27.G22 | length 20.8
  Top Layer w0.09: U27.G22@102.4,76 102.41,75.99 103.006,75.99 103.331,75.665 103.683,75.665 103.99,75.972 104.189,75.972 104.495,75.665 104.876,75.665 105.18,75.969 105.385,75.969 105.689,75.665 106.216,75.665 106.315,75.764 106.315,78.269 106.708,78.662 107.362,78.662 107.458,78.759 107.458,79.176 107.551,79.268 107.685,79.268 107.771,79.182 107.771,76.799 107.851,76.719 108.553,76.719 108.659,76.825 108.659,79.545 108.748,79.634 109.978,79.634 110.105,79.506 110.105,79.033 110.239,78.9 110.455,78.9 110.627,78.728 110.751,78.728 111.417,79.395 111.57,79.395 111.762,79.586 112.659,79.586 U2.Y11@112.935,79.31
DDR_DQ10_A: U2.E11 U27.L21 | length 17.7
  Top Layer w0.09: U27.L21@101.6,72.8 101.825,72.575 102.208,72.575 102.453,72.33 104.792,72.33 104.98,72.141 104.98,71.39 105.065,71.305 105.767,71.305 105.85,71.388 105.85,72.19 106.175,72.515 107.01,72.515 107.74,71.785 108.027,71.785 108.757,72.515 109.836,72.515 110.135,72.216 110.135,69.625 110.423,69.337 110.423,68.869 110.646,68.647 111.078,68.647 111.611,69.18 112.63,69.18 U2.E11@112.95,69.5
DDR_DQ10_B: U2.V11 U27.G21 | length 21.8
  Top Layer w0.09: U27.G21@101.6,76 101.9,75.7 102.886,75.7 103.211,75.375 103.804,75.375 104.037,75.608 104.142,75.608 104.375,75.375 104.997,75.375 105.221,75.6 105.343,75.6 105.568,75.375 106.577,75.375 106.683,75.482 106.683,75.807 106.605,75.885 106.605,78.149 106.828,78.372 107.406,78.372 107.481,78.296 107.481,76.513 107.565,76.429 108.853,76.429 108.949,76.525 108.949,79.247 109.046,79.344 109.601,79.344 109.815,79.13 109.815,78.075 109.892,77.998 110.045,77.998 110.147,78.101 110.147,78.472 110.26,78.585 110.36,78.585 110.626,78.319 110.752,78.319 111.033,78.6 111.225,78.6 111.33,78.705 111.595,78.705 112.03,78.27 112.63,78.27 U2.V11@112.95,77.95
DDR_DQ11_A: U2.F11 U27.L22 | length 17.1
  Top Layer w0.09: U27.L22@102.4,72.8 102.725,72.8 102.819,72.707 105.075,72.707 105.27,72.512 105.27,71.676 105.351,71.595 105.475,71.595 105.56,71.681 105.56,72.665 105.7,72.805 107.499,72.805 107.593,72.711 107.593,72.342 107.744,72.192 107.884,72.192 108.028,72.336 108.028,72.658 108.175,72.805 110.2,72.805 110.425,72.58 110.425,69.745 110.74,69.43 110.94,69.43 111.536,70.025 111.75,70.025 111.95,69.825 112.625,69.825 U2.F11@112.95,70.15
DDR_DQ11_B: U2.U11 U27.G20 | length 22.4
  Top Layer w0.09: U27.G20@100.8,76 101.3,75.5 102.675,75.5 103.09,75.085 105.117,75.085 105.211,75.179 105.354,75.179 105.448,75.085 106.89,75.085 106.973,75.168 106.973,75.927 106.895,76.005 106.895,78.009 106.968,78.082 107.098,78.082 107.191,77.989 107.191,76.244 107.297,76.139 108.557,76.139 108.698,75.998 108.873,75.998 109.014,76.139 109.147,76.139 109.239,76.231 109.239,78.972 109.321,79.054 109.444,79.054 109.525,78.972 109.525,77.73 109.687,77.568 110.025,77.568 110.267,77.811 110.653,77.811 110.999,78.156 111.171,78.156 111.255,78.072 111.255,77.95 111.35,77.855 111.762,77.855 111.968,77.649 112.601,77.649 U2.U11@112.95,77.3
DDR_DQ12_A: U2.F9 U27.T22 | length 20.6
  Top Layer w0.09: U27.T22@102.4,68.8 102.405,68.795 103.651,68.795 103.721,68.725 107.203,68.725 110.733,65.195 113.657,65.195 113.897,65.435 114.733,65.435 116.02,66.722 116.02,67.025 116.02,68.597 115.449,69.169 114.465,69.169 114.255,69.378 114.255,69.855 U2.F9@114.55,70.15
DDR_DQ12_B: U2.U9 U27.J21 | length 22.2
  Top Layer w0.09: U27.J21@101.6,74.4 102.162,74.4 102.307,74.255 107.682,74.255 107.804,74.377 107.804,75.227 107.886,75.309 108.037,75.309 108.11,75.236 108.11,74.382 108.238,74.255 109.396,74.255 109.483,74.342 109.483,75.233 109.555,75.305 109.708,75.305 109.785,75.228 109.785,74.326 110.177,73.935 113.368,73.935 113.466,74.033 ; 113.466,74.033 113.559,74.125 114.326,74.125 114.545,74.345 114.605,74.405 115.518,74.405 116.095,74.982 116.095,75.836 115.645,76.286 115.645,76.772 115.428,76.99 115.225,76.99 114.915,77.3 U2.U9@114.55,77.3
DDR_DQ13_A: U2.E9 U27.R20 | length 23
  Top Layer w0.09: U27.R20@100.8,69.6 101.19,69.211 101.607,69.211 101.982,68.835 101.982,68.801 102.278,68.505 103.531,68.505 103.634,68.402 107.116,68.402 110.613,64.905 113.777,64.905 114.017,65.145 114.853,65.145 116.31,66.602 116.31,69.189 116.121,69.378 116.121,69.492 115.818,69.795 114.845,69.795 U2.E9@114.55,69.5
DDR_DQ13_B: U2.V9 U27.J20 | length 22.7
  Top Layer w0.09: U27.J20@100.8,74.4 100.8,74.125 101.25,73.675 109.596,73.675 109.756,73.515 114.536,73.515 114.846,73.825 115.476,73.825 116.475,74.825 116.475,76.087 116.2,76.362 116.2,76.831 116.391,77.022 116.391,77.659 116.225,77.825 116.225,78.273 115.937,78.562 115.729,78.562 115.413,78.245 115.258,78.245 115.082,78.421 114.874,78.421 114.796,78.344 114.796,78.196 U2.V9@114.55,77.95
DDR_DQ14_A: U2.C9 U27.R21 | length 19.7
  Top Layer w0.09: U27.R21@101.6,69.6 101.627,69.6 102.13,69.098 102.773,69.098 102.991,69.315 103.685,69.315 103.985,69.015 106.489,69.015 106.674,69.2 107.026,69.2 107.21,69.015 107.323,69.015 110.133,66.205 110.844,66.205 110.926,66.124 110.926,65.975 110.85,65.9 110.728,65.9 110.644,65.816 110.644,65.694 110.853,65.485 113.536,65.485 113.776,65.725 114.613,65.725 115.71,66.823 115.71,67.125 115.58,67.255 115.228,67.255 115.055,67.428 115.055,68.078 114.933,68.2 U2.C9@114.55,68.2
DDR_DQ14_B: U2.Y9 U27.K20 | length 23.1
  Top Layer w0.09: U27.K20@100.8,73.6 101.015,73.385 109.471,73.385 109.551,73.305 114.747,73.305 114.973,73.531 115.45,73.531 116.665,74.746 116.665,76.305 116.599,76.371 116.599,78.31 116.28,78.629 116.28,78.978 115.712,79.545 115.12,79.545 114.825,79.25 U2.Y9@114.55,79.25
DDR_DQ15_A: U2.B9 U27.R22 | length 18.7
  Top Layer w0.09: U27.R22@102.4,69.6 102.455,69.6 102.75,69.895 107.171,69.895 107.466,69.6 107.574,69.6 107.869,69.895 108.013,69.895 108.125,69.783 108.125,69.1 108.217,69.009 108.353,69.009 108.429,69.084 108.429,70.193 108.511,70.275 108.646,70.275 108.725,70.195 108.725,68.433 110.373,66.785 111.085,66.785 111.805,66.065 113.296,66.065 113.536,66.305 114.373,66.305 114.845,66.778 114.845,67.04 114.554,67.331 114.554,67.546 U2.B9@114.55,67.55
DDR_DQ15_B: U2.AA9 U27.L19 | length 24.8
  Top Layer w0.09: U27.L19@100,72.8 100.295,73.095 115.283,73.095 116.855,74.667 116.855,78.528 116.654,78.729 116.654,79.014 115.473,80.195 114.845,80.195 U2.AA9@114.55,79.9
DDR_DQMI0_A: U2.C3 U27.W21 | length 25.5
  Top Layer w0.09: U27.W21@101.6,66.4 101.606,66.406 101.957,66.406 102.245,66.695 102.522,66.695 103.367,65.85 103.995,65.85 105.205,64.64 105.396,64.64 105.898,65.142 106.061,65.142 106.524,64.679 106.524,64.527 106.132,64.135 106.132,63.974 106.913,63.192 107.14,63.192 107.519,63.571 107.794,63.571 108.061,63.303 108.061,63.043 108.189,62.915 116.803,62.915 119.885,65.997 119.885,66.672 119.851,66.706 119.851,67.7 U2.C3@119.35,68.2
DDR_DQMI0_B: U2.Y3 U27.E21 | length 26.4
  Top Layer w0.09: U27.E21@101.6,77.6 101.603,77.597 101.82,77.597 101.892,77.525 103.52,77.525 106.714,80.718 107.482,80.718 107.753,80.989 107.753,81.304 107.516,81.541 107.516,81.676 108.025,82.185 108.218,82.185 108.54,81.864 109.705,81.864 109.785,81.944 109.785,82.33 109.865,82.41 109.992,82.41 110.075,82.327 110.075,82.117 110.21,81.982 110.554,81.982 110.655,81.881 110.655,81.011 110.741,80.925 110.863,80.925 110.945,81.007 110.945,82.338 111.017,82.41 111.161,82.41 111.241,82.33 111.241,81.807 111.334,81.715 117.146,81.715 117.385,81.954 117.561,81.954 117.941,81.575 117.941,80.99 118.052,80.879 ; 118.056,80.879 118.056,80.345 118.244,80.157 118.244,79.789 118.488,79.545 118.673,79.545 118.968,79.25 U2.Y3@119.35,79.25
DDR_DQMI1_A: U2.C10 U27.P20 | length 20.2
  Top Layer w0.09: U27.P20@100.8,70.4 101.05,70.15 101.753,70.15 101.981,69.922 101.981,69.602 102.278,69.305 102.57,69.305 102.87,69.605 103.805,69.605 104.105,69.305 104.291,69.305 104.591,69.605 104.792,69.605 105.087,69.31 105.305,69.31 105.6,69.605 105.816,69.605 106.116,69.305 106.369,69.305 106.669,69.605 107.03,69.605 107.325,69.31 107.438,69.31 110.253,66.495 110.964,66.495 111.684,65.775 113.416,65.775 113.656,66.015 114.493,66.015 115.035,66.558 115.035,67.119 114.845,67.309 114.845,67.672 114.668,67.85 114.1,67.85 U2.C10@113.75,68.2
DDR_DQMI1_B: U2.Y10 U27.H20 | length 23.4
  Top Layer w0.09: U27.H20@100.8,75.2 100.8,75.197 101.154,74.843 101.154,74.436 101.625,73.965 109.723,73.965 109.963,73.725 113.569,73.725 113.679,73.835 114.446,73.835 114.725,74.115 115.497,74.115 116.285,74.903 116.285,76.009 115.925,76.369 115.925,76.825 116.145,77.045 116.145,77.418 115.968,77.595 115.265,77.595 115.21,77.65 114.403,77.65 114.242,77.811 114.242,79.025 114.017,79.25 U2.Y10@113.75,79.25
DDR_DQS0_A_N: U2.E3 U27.W20 | length 28.3
  Top Layer w0.09: U27.W20@100.8,66.4 101.019,66.619 101.358,66.619 101.624,66.885 102.742,66.885 103.487,66.14 103.966,66.14 104.505,66.68 104.631,66.68 104.727,66.584 104.727,66.406 104.575,66.254 104.575,65.68 105.031,65.224 105.57,65.224 105.896,65.55 106.063,65.55 106.953,64.66 106.953,64.546 106.644,64.236 106.644,63.904 106.86,63.688 107.226,63.688 107.596,64.058 108.141,64.058 108.228,63.972 108.228,63.547 108.57,63.205 116.683,63.205 118.97,65.492 118.97,66.549 119.055,66.634 119.055,68.322 119.288,68.555 119.473,68.555 119.645,68.728 119.645,69.28 U2.E3@119.35,69.575
DDR_DQS0_A_P: U2.D3 U27.V20 | length 27
  Top Layer w0.09: U27.V20@100.8,67.2 101.131,66.869 101.254,66.869 101.52,67.135 102.846,67.135 103.591,66.39 103.862,66.39 104.402,66.93 104.734,66.93 104.977,66.687 104.977,66.302 104.825,66.15 104.825,65.784 105.135,65.474 105.466,65.474 105.792,65.8 106.166,65.8 107.203,64.763 107.203,64.442 106.894,64.133 106.894,64.007 106.963,63.938 107.122,63.938 107.493,64.308 108.245,64.308 108.478,64.075 108.478,63.651 108.673,63.455 116.58,63.455 118.72,65.596 118.72,66.653 118.845,66.778 118.845,68.402 U2.D3@119.35,68.907
DDR_DQS0_B_N: U2.V3 U27.D22 | length 26
  Top Layer w0.09: U27.D22@102.4,78.4 103.222,78.4 106.583,81.761 106.583,81.917 107.906,83.24 111.779,83.24 112.071,82.947 112.071,82.656 112.182,82.545 112.8,82.545 112.969,82.713 112.969,83.007 113.201,83.24 113.542,83.24 113.773,83.008 113.773,82.722 113.95,82.545 114.424,82.545 114.646,82.768 114.646,83.041 114.845,83.24 115.229,83.24 115.44,83.029 115.44,82.78 115.675,82.545 116.802,82.545 117.225,82.968 117.721,82.968 119.855,80.834 119.855,78.74 119.705,78.59 119.705,78.453 119.385,78.132 119.385,77.984 U2.V3@119.35,77.95
DDR_DQS0_B_P: U2.W3 U27.D21 | length 25.7
  Top Layer w0.09: U27.D21@101.6,78.4 101.942,78.4 102.237,78.105 102.605,78.105 102.65,78.15 103.325,78.15 106.833,81.658 106.833,81.814 108.009,82.99 111.675,82.99 111.821,82.844 111.821,82.553 112.079,82.295 112.904,82.295 113.219,82.61 113.219,82.903 113.305,82.99 113.438,82.99 113.523,82.904 113.523,82.618 113.847,82.295 114.527,82.295 114.896,82.664 114.896,82.913 114.973,82.99 115.111,82.99 115.19,82.91 115.19,82.676 115.571,82.295 116.906,82.295 117.328,82.718 117.618,82.718 119.645,80.69 119.645,78.883 119.362,78.6 U2.W3@119.35,78.6
DDR_DQS1_A_N: U2.E10 U27.N21 | length 20
  Top Layer w0.09: U27.N21@101.6,71.2 101.571,71.2 101.335,70.965 101.335,70.812 101.453,70.695 102.105,70.695 102.359,70.441 ; 102.365,70.435 103.193,70.435 103.272,70.515 103.272,71.169 103.509,71.405 103.876,71.405 104.106,71.176 104.106,70.753 104.424,70.435 107.907,70.435 108.304,70.832 108.853,70.832 109.265,70.419 109.265,68.657 110.161,67.761 110.872,67.761 112.028,66.605 113.073,66.605 113.235,66.768 113.235,68.689 113.477,68.93 113.477,68.99 113.745,69.258 U2.E10@113.745,69.494
DDR_DQS1_A_P: U2.D10 U27.N20 | length 20.1
  Top Layer w0.09: U27.N20@100.8,71.2 100.847,71.2 101.085,70.962 101.085,70.709 101.349,70.445 102.001,70.445 102.261,70.185 103.296,70.185 103.522,70.411 103.522,71.065 103.612,71.155 103.773,71.155 103.856,71.073 103.856,70.649 104.32,70.185 108.011,70.185 108.408,70.582 108.749,70.582 109.015,70.316 109.015,68.553 110.057,67.511 110.769,67.511 111.925,66.355 113.176,66.355 113.465,66.644 113.465,68.565 U2.D10@113.75,68.85
DDR_DQS1_B_N: U2.V10 U27.H21 | length 22.5
  Top Layer w0.09: U27.H21@101.533,75.175 101.895,75.175 102.165,74.905 102.312,74.905 102.672,74.545 107.288,74.545 107.514,74.771 107.514,75.518 107.595,75.599 108.322,75.599 108.4,75.52 108.4,74.769 108.624,74.545 109.001,74.545 109.193,74.736 109.193,75.519 109.269,75.595 109.556,75.595 109.779,75.819 109.779,76.95 109.857,77.028 109.999,77.028 110.075,76.952 110.075,74.446 110.367,74.155 113.176,74.155 113.465,74.444 113.465,77.665 U2.V10@113.75,77.95
DDR_DQS1_B_P: U2.W10 U27.H22 | length 21.9
  Top Layer w0.09: U27.H22@102.4,75.2 102.4,75.171 102.776,74.795 107.184,74.795 107.264,74.875 107.264,75.621 107.492,75.849 108.425,75.849 108.65,75.624 108.65,74.873 108.728,74.795 108.859,74.795 108.943,74.878 108.943,75.623 109.165,75.845 109.452,75.845 109.529,75.923 109.529,77.054 109.754,77.278 110.102,77.278 110.325,77.055 110.325,74.55 110.47,74.405 113.073,74.405 113.235,74.568 113.235,76.625 113.235,77.789 113.395,77.949 113.395,78.245 U2.W10@113.75,78.6
DDR_RESETN: R156.2 U2.T11 U27.F18 | length 15.6
  Top Layer w0.09: U27.F18@99.2,76.8 99.6,77.2 v4(99.6,77.25) ; v4@112.55,77.075 112.569,77.075 112.95,76.693 U2.T11@112.95,76.65
  Bottom Layer w0.09: v4@99.6,77.225 100.111,77.736 105.439,77.736 105.643,77.532 111.018,77.532 111.395,77.155 112.175,77.155 112.215,77.115 112.51,77.115 112.55,77.075 113.3,77.075 R156.2@113.425,76.95
  other v4: 112.55,77.09
eMMC.SDMMC2_CK: R49.1 U24.M6 U27.A20 | length 19.6
  Top Layer w0.09: 110.73,89.925 110.73,90.16 ; 110.73,90.425 110.73,90.66 ; 110.73,90.925 110.73,91.16
  Top Layer w0.11: U27.A20@100.796,80.804 100.796,83.828 105.88,88.912 107.354,88.912 108.036,89.593 110.577,89.593 110.73,89.746 110.73,89.925 ; 110.73,90.16 110.73,90.292 ; 110.73,90.294 110.73,90.425 ; 110.73,90.66 110.73,90.792 ; 110.73,90.794 110.73,90.925 ; 110.73,91.16 110.73,91.259 110.65,91.339 110.65,91.719 110.76,91.83 110.76,92.043 v2(110.98,92.262) 111.26,92.542 U24.M6@111.48,92.542
  Bottom Layer w0.11: v2@111,92.25 111.337,92.25 111.651,91.936 R49.1@111.746,91.936
eMMC.SDMMC2_CMD: R37.1 U24.M5 U27.F17 | length 23.4
  Top Layer w0.09: U27.F17@98.4,76.8 98.405,76.805 98.405,77.107 98.818,77.52 98.818,77.621 99.312,78.115 99.318,78.115 99.6,78.397 99.6,78.403 100.112,78.915 100.118,78.915 100.285,79.082 100.285,79.088 100.506,79.309 100.506,80.103 100.515,80.112 100.515,80.118 100.682,80.285 100.688,80.285 101.085,80.682 101.085,81.103 ; 111.23,89.925 111.23,90.16 ; 111.23,90.425 111.23,90.66 ; 111.23,90.925 111.23,91.16
  Top Layer w0.11: 101.085,81.103 101.175,81.193 101.175,82.553 107.152,88.53 107.752,88.53 108.506,89.283 110.706,89.283 110.709,89.286 110.717,89.286 111.23,89.799 111.23,89.925 ; 111.23,90.16 111.23,90.292 ; 111.23,90.294 111.23,90.425 ; 111.23,90.66 111.23,90.792 ; 111.23,90.794 111.23,90.925 ; 111.23,91.16 111.23,91.347 v2(111.005,91.572) U24.M5@111.475,92.042
  Bottom Layer w0.11: v2(111.005,91.572) 111.083,91.572 111.324,91.331 111.619,91.331 R37.1@111.775,91.175
eMMC.SDMMC2_D0: R44.1 U24.A3 U27.B19 | length 15.6
  Top Layer w0.09: 99.715,81.085 99.715,80.682 100,80.397 U27.B19@100,80
  Top Layer w0.11: 99.715,81.085 99.749,81.119 99.749,86.116 104.208,90.575 v1(104.975,90.575) 105.442,91.042 U24.A3@105.98,91.042
  Bottom Layer w0.11: v1(104.975,90.575) 105.795,90.575 R44.1@105.95,90.73
eMMC.SDMMC2_D1: U24.A4 U27.E17 | length 18.4
  Top Layer w0.09: U27.E17@98.4,77.6 98.915,78.115 98.915,78.518 99.074,78.677 99.074,78.709 99.28,78.915 99.318,78.915 99.525,79.122 99.525,79.715 99.417,79.823 99.417,80.373 99.244,80.546 99.244,80.754 ; 104.103,91.535 105.973,91.535 U24.A4@105.98,91.542 ; U24.A4@106.04,91.472 U24.A4@106.05,91.482
  Top Layer w0.11: 99.249,80.759 99.249,86.681 104.103,91.535
eMMC.SDMMC2_D2: U24.A5 U27.C18 | length 16.9
  Top Layer w0.09: 99.045,80.279 99.045,81.006 ; 99.047,80.279 99.2,80.126 U27.C18@99.2,79.2
  Top Layer w0.11: 99.045,81.006 98.981,81.07 98.981,86.914 104.11,92.042 U24.A5@105.98,92.042
eMMC.SDMMC2_D3: U24.B2 U27.C19 | length 14.8
  Top Layer w0.09: U27.C19@100,79.2 100.298,79.498 100.298,81.2 ; 106.409,89.563 106.73,89.884 106.73,90.292 U24.B2@106.48,90.542
  Top Layer w0.11: 100.298,81.2 100.506,81.408 100.506,84.559 105.511,89.563 106.409,89.563
eMMC.SDMMC2_D4: U24.B3 U27.A19 | length 14.5
  Top Layer w0.09: 105.577,90.493 105.876,90.792 106.23,90.792 U24.B3@106.48,91.042
  Top Layer w0.11: U27.A19@100,80.8 100,81.5 100.239,81.739 100.239,85.512 100.506,85.779 100.954,85.779 101.725,86.55 101.725,87.4 102.2,87.875 103.25,87.875 103.716,88.341 103.716,89.206 104.035,89.525 104.9,89.525 105.577,90.202 105.577,90.493
eMMC.SDMMC2_D5: U24.B4 U27.D18 | length 17.4
  Top Layer w0.09: U27.D18@99.2,78.4 99.485,78.685 99.485,78.813 99.705,79.033 99.705,79.804 ; 105.226,91.157 105.361,91.292 106.23,91.292 U24.B4@106.48,91.542
  Top Layer w0.11: 99.705,79.804 99.607,79.902 99.607,80.492 99.495,80.604 99.495,86.363 104.289,91.157 105.226,91.157
eMMC.SDMMC2_D6: U24.B5 U27.E16 | length 20.5
  Top Layer w0.09: U27.E16@97.6,77.6 98.09,78.09 98.487,78.09 98.512,78.115 98.518,78.115 98.71,78.307 98.71,78.681 98.865,78.836 98.865,80.718 98.72,80.863 ; 105.611,92.292 106.23,92.292
  Top Layer w0.11: 98.728,80.863 98.728,87.21 103.923,92.406 104.817,92.406 104.93,92.292 105.611,92.292 ; 106.23,92.292 U24.B5@106.48,92.042
eMMC.SDMMC2_D7: U24.B6 U27.D17 | length 19.9
  Top Layer w0.09: U27.D17@98.4,78.4 98.4,78.797 98.685,79.082 98.685,80.555 98.476,80.763 ; 105.862,92.792 106.098,92.792
  Top Layer w0.11: 98.476,80.763 98.476,87.381 104.293,93.197 105.391,93.197 105.796,92.792 105.862,92.792 ; 106.098,92.792 106.23,92.792 U24.B6@106.48,92.542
